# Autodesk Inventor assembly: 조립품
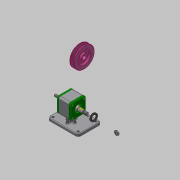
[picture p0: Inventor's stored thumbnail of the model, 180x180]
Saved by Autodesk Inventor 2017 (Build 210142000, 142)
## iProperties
Part Number: 조립품
Material: 일반
Document SubType Name: Assembly
Designer: mrc
Author: mrc
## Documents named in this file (10)
- C:\Users\mrc\Desktop\701106V1026\조립품.iam
- C:\Users\mrc\Desktop\701106V1026\너트 M10x1.ipt
- C:\Users\mrc\Desktop\701106V1026\베어링 6004.ipt
- C:\Users\mrc\Desktop\701106V1026\본체.ipt
- C:\Users\mrc\Desktop\701106V1026\V-벨트풀리.ipt
- C:\Users\mrc\Desktop\701106V1026\볼트 M4.ipt
- C:\Users\mrc\Desktop\701106V1026\오일 실 17 30 5.ipt
- C:\Users\mrc\Desktop\701106V1026\축.ipt
- C:\Users\mrc\Desktop\701106V1026\커버.ipt
- C:\Users\mrc\Desktop\701106V1026\키 5 x 5 x 12.ipt
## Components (1 placed, 1 different names)
1. V-벨트풀리:2
